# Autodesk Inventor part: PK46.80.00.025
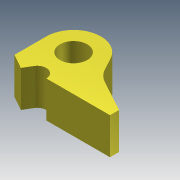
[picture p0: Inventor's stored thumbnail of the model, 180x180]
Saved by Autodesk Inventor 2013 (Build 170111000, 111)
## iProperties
Created: 2005-05
Part Number: PK46.80.00.025
Material: Steel, Mild
Document SubType Name: Modeling
Designer: salex
Manufacturer: Standard
Standards Organization: Custom
Density: 7.86 g/cm^3
Mass: 1312.57 g
Surface Area: 249.638 cm^2
Volume: 166.994 cm^3
Author: salex
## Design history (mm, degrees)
sketch "Эскиз1"
  geometry: L1 (-30, 0)-(-30, -35); L2 (-30, -35)-(-14, -44); L3 (-14, -44)-(-8.6, -34.898); L4 (10, -40)-(80, -40); L5 (80, -40)-(80, -30); L6 (80, -30)-(45.683, -11.363); L7 (33.53, 0.882)-(26.471, 14.118); L8 (-10.328, -30)-(13.832, -30); L9 (-230.71, 77.605)-(196.61, -162.182) reference; C1 r 15 at (0, 0); A1 r 30 centre (0, 0) between (26.471, 14.118) and (-30, 0); A2 r 10 centre (0, -40) between (10, -40) and (-8.6, -34.898); A3 r 30 centre (60, 15) between (33.53, 0.882) and (45.683, -11.363)
  constraints: 16 end point, 6 point on circle, 6 tangent, 4 centre point, 3 perpendicular, 1 coincident, 1 vertical, 1 other
  dimensions: "d0" = 30 radius of A1; "d1" = 30 diameter of C1; "d2" = 30 radius of A3; "d3" = 40 distance from line of C1.centre L4; "d4" = 10 distance of L4.end L5.end; "d5" = 80 distance from line of L5 C1.centre; "d6" = 60 horizontal distance of A3.centre C1.centre; "d7" = 55 distance from line of A3.centre L4; "d8" = 70 distance of L4.start L4.end; "d9" = 10 radius of A2; "d10" = 44 vertical distance of L2.end C1.centre; "d11" = 35 vertical distance of L1.end C1.centre; "d12" = 16 distance from line of L2.end L1; "d13" = 30 distance from line of C1.centre L8
extrude "Выдавливание1" new body sketch "Эскиз1" distance "d14" = 40; taper "d15" = 0 deg
body "Solid1"
node "ЗаимстЛин1"
